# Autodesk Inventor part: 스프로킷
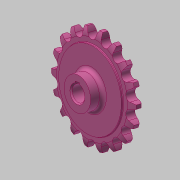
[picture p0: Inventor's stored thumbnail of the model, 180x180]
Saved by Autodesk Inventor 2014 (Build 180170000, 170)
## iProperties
Created: 2016-03
Part Number: 스프로킷
Material: 강철, 탄소
Document SubType Name: Modeling
Designer: mduedu
Density: 7.87 g/cm^3
Mass: 301.818 g
Surface Area: 124.882 cm^2
Volume: 38.3505 cm^3
Appearance: 분홍색
Author: mduedu
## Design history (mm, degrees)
sketch "스케치1"
  geometry: L1 (0, 5)-(29.5, 5); L2 (29.5, 5)-(29.5, 4.1); L3 (30, 3.6)-(33.625, 3.6); L4 (40, 2)-(40, 0); L5 (40, 0)-(0, 0); L6 (0, 0)-(0, 5); L7 (0, -5)-(29.5, -5); L8 (29.5, -5)-(29.5, -4.1); L9 (30, -3.6)-(33.625, -3.6); L10 (40, -2)-(40, 0); L11 (0, 0)-(0, -5); A1 r 13.5 centre (33.625, -9.9) between (40, 2) and (33.625, 3.6); A2 r 13.5 centre (33.625, 9.9) between (33.625, -3.6) and (40, -2); A3 r 0.5 centre (30, 4.1) between (29.5, 4.1) and (30, 3.6); A4 r 0.5 centre (30, -4.1) between (30, -3.6) and (29.5, -4.1); 2 further points
  constraints: 22 end point, 8 point on circle, 6 symmetric about line, 5 tangent, 4 centre point, 4 parallel, 4 point on line, 1 equal radius, 1 horizontal, 1 perpendicular, 1 other
  dimensions: "d0" = 80 diameter of L4 L6; "d2" = 59 diameter of L2 L6; "d3" = 1.6 vertical distance of L4.start L3.end; "d4" = 3.6 distance from line of L4.end L3; "d5" = 5 distance between parallel lines of L5 L1; "d6" = 13.5 radius of A1; "d15" = 0.5 radius of A3
revolve "회전1" sketch "스케치1" stored, may be unused: angle "d7" = 90 deg
sketch "스케치2" dims "d8" = 65.2, "d11" = 80
  geometry: L1 (0, 0)-(0, 32.6); A1 r 36.57 centre (0, 0) between (-16.231, 32.771) and (0, 36.57); A2 r 3.97 centre (0, 36.57) between (-3.866, 35.665) and (0, 32.6); A3 r 12.7 centre (-16.231, 32.771) between (-3.866, 35.665) and (-5.534, 39.615); A4 r 12.7 centre (16.231, 32.771) between (5.534, 39.615) and (3.866, 35.665); A5 r 3.97 centre (0, 36.57) between (0, 32.6) and (3.866, 35.665); A6 r 40 centre (0, 0) between (5.534, 39.615) and (-5.534, 39.615); 2 further points
  constraints: 12 point on circle, 6 centre point, 4 coincident, 3 symmetric about line, 2 end point, 1 point on line, 1 tangent, 1 vertical, 1 vertical alignment, 7 other
  dimensions: "d10" = 73.14 diameter of A1; "d12" = 12.7 radius of A3
extrude "돌출1" cut sketch "스케치2" stored distance "d13" = 10; taper "d14" = 0 deg
sketch "스케치3"
  geometry: C1 r 12.5 at (0, 0); 1 further point
  constraints: 1 centre point, 1 coincident
  dimensions: "d19" = 25 diameter of C1
extrude "돌출2" join sketch "스케치3" distance "d20" = 10; taper "d21" = 0 deg
fillet "모깎기1" dims "d22" = 3
sketch "스케치4"
  geometry: L1 (-2, 0)-(2, 0); L2 (2, 0)-(2, 7.8); L3 (2, 7.8)-(-2, 7.8); L4 (-2, 7.8)-(-2, 0); C1 r 6 at (0, 0); 2 further points
  constraints: 8 end point, 2 coincident, 2 parallel, 1 centre point, 1 horizontal, 1 midpoint, 1 perpendicular
  dimensions: "d23" = 12 diameter of C1; "d25" = 4 distance of L2.end L3.end; "d26" = 7.8 distance of L1.end L2.end
extrude "돌출3" cut sketch "스케치4" stored distance "d27" = 8; taper "d28" = 0 deg
chamfer "모따기2" distance "d42" = 1; stored, may be unused: second distance "d43" = 2, angle "d44" = 45 deg
node "솔리드1"
pattern_circular "원형 패턴1" dims angle "d17" = 360 deg
